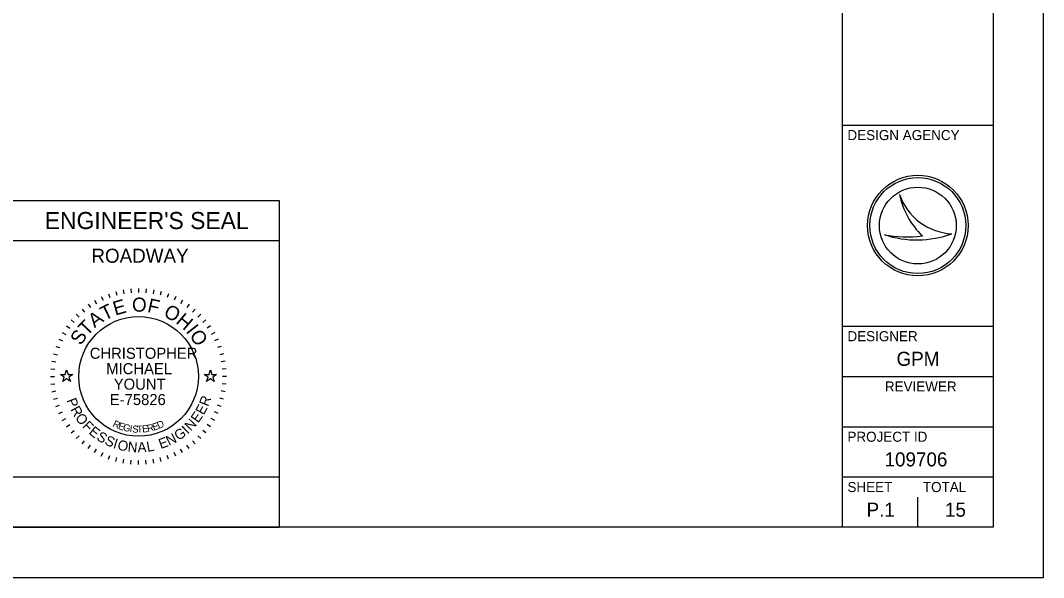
# Model space of a CAD drawing. Extents: x 0 to 34, y 0 to 22.
# Drawn here: x 23.83 to 34, y 0 to 5.54 of the extents above; entities that cross this region are included whole.
import ezdxf

# ---------------------------------------------------------------- set-up
doc = ezdxf.new("R2010")
doc.units = 0
for name, color, linetype in [('Default', 7, 'Continuous'), ('SH_Border', 7, 'Continuous'), ('SH_Cut_Line', 7, 'Continuous'), ('SH_Data', 7, 'Continuous')]:
    doc.layers.add(name, color=color, linetype=linetype)

msp = doc.modelspace()

# ---------------------------------------------------------------- linework, layer by layer
at = {"layer": 'Default'}
for points in [[(24.224, 2.02), (24.271, 2.02), (24.285, 2.065), (24.299, 2.02), (24.346, 2.02), (24.308, 1.992), (24.323, 1.948), (24.285, 1.975), (24.247, 1.948), (24.262, 1.992)], [(25.654, 2.02), (25.701, 2.02), (25.715, 2.065), (25.729, 2.02), (25.776, 2.02), (25.738, 1.992), (25.753, 1.948), (25.715, 1.975), (25.677, 1.948), (25.692, 1.992)]]:
    msp.add_lwpolyline(points, close=True, dxfattribs=at)
at = {"layer": 'SH_Border'}
for p, q in [((32, 0.5), (32, 21.5)), ((32, 4.5), (33.5, 4.5)), ((32, 2.5), (33.5, 2.5)), ((32, 2), (33.5, 2)), ((32, 1.5), (33.5, 1.5)), ((32, 1), (33.5, 1))]:
    msp.add_line(p, q, dxfattribs=at)
msp.add_lwpolyline([(1.5, 21.5), (33.5, 21.5), (33.5, 0.5), (1.5, 0.5)], close=True, dxfattribs=at)
at = {"layer": 'SH_Cut_Line'}
msp.add_lwpolyline([(0, 0), (34, 0), (34, 22), (0, 22)], close=True, dxfattribs=at)
at = {"layer": 'SH_Data'}
for p, q in [((32.567, 3.81), (32.567, 3.81)), ((23.6, 3.75), (26.4, 3.75)), ((26.4, 3.75), (26.4, 0.5)), ((32.75, 3.5), (32.75, 3.5)), ((32.417, 3.41), (32.417, 3.41)), ((33.087, 3.419), (33.087, 3.419)), ((23.6, 3.35), (26.4, 3.35)), ((24.848, 2.862), (24.855, 2.822)), ((24.924, 2.872), (24.927, 2.832)), ((25, 2.875), (25, 2.835)), ((25.076, 2.872), (25.073, 2.832)), ((25.152, 2.862), (25.145, 2.822)), ((24.563, 2.758), (24.583, 2.723)), ((24.63, 2.793), (24.647, 2.757)), ((24.701, 2.822), (24.714, 2.785)), ((24.774, 2.845), (24.784, 2.807)), ((25.226, 2.845), (25.216, 2.807)), ((25.299, 2.822), (25.286, 2.785)), ((25.37, 2.793), (25.353, 2.757)), ((25.437, 2.758), (25.417, 2.723)), ((24.438, 2.67), (24.463, 2.64)), ((24.498, 2.717), (24.521, 2.684)), ((25.502, 2.717), (25.479, 2.684)), ((25.562, 2.67), (25.537, 2.64)), ((24.33, 2.562), (24.36, 2.537)), ((24.381, 2.619), (24.41, 2.59)), ((25.619, 2.619), (25.59, 2.59)), ((25.67, 2.562), (25.64, 2.537)), ((24.283, 2.502), (24.316, 2.479)), ((25.717, 2.502), (25.684, 2.479)), ((24.207, 2.37), (24.243, 2.353)), ((24.242, 2.438), (24.277, 2.418)), ((25.758, 2.438), (25.723, 2.418)), ((25.793, 2.37), (25.757, 2.353)), ((24.178, 2.299), (24.215, 2.286)), ((25.822, 2.299), (25.785, 2.286)), ((24.138, 2.152), (24.178, 2.145)), ((24.155, 2.226), (24.193, 2.216)), ((25.845, 2.226), (25.807, 2.216)), ((25.862, 2.152), (25.822, 2.145)), ((24.128, 2.076), (24.168, 2.073)), ((25.872, 2.076), (25.832, 2.073)), ((24.125, 2), (24.165, 2)), ((25.875, 2), (25.835, 2)), ((24.128, 1.924), (24.168, 1.927)), ((24.138, 1.848), (24.178, 1.855)), ((25.862, 1.848), (25.822, 1.855)), ((25.872, 1.924), (25.832, 1.927)), ((24.155, 1.774), (24.193, 1.784)), ((25.845, 1.774), (25.807, 1.784)), ((24.178, 1.701), (24.215, 1.714)), ((24.207, 1.63), (24.243, 1.647)), ((25.793, 1.63), (25.757, 1.647)), ((25.822, 1.701), (25.785, 1.714)), ((24.242, 1.563), (24.277, 1.583)), ((25.758, 1.563), (25.723, 1.583)), ((24.283, 1.498), (24.316, 1.521)), ((24.33, 1.438), (24.36, 1.463)), ((25.67, 1.438), (25.64, 1.463)), ((25.717, 1.498), (25.684, 1.521)), ((24.381, 1.381), (24.41, 1.41)), ((24.438, 1.33), (24.463, 1.36)), ((25.562, 1.33), (25.537, 1.36)), ((25.619, 1.381), (25.59, 1.41)), ((24.498, 1.283), (24.521, 1.316)), ((24.563, 1.242), (24.583, 1.277)), ((24.63, 1.207), (24.647, 1.243)), ((25.37, 1.207), (25.353, 1.243)), ((25.437, 1.242), (25.417, 1.277)), ((25.502, 1.283), (25.479, 1.316)), ((24.701, 1.178), (24.714, 1.215)), ((24.774, 1.155), (24.784, 1.193)), ((24.848, 1.138), (24.855, 1.178)), ((24.924, 1.128), (24.927, 1.168)), ((25, 1.125), (25, 1.165)), ((25.076, 1.128), (25.073, 1.168)), ((25.152, 1.138), (25.145, 1.178)), ((25.226, 1.155), (25.216, 1.193)), ((25.299, 1.178), (25.286, 1.215)), ((32.75, 0.5), (32.75, 0.8)), ((32.375, 0.675), (32.375, 0.675)), ((23.6, 0.5), (26.4, 0.5))]:
    msp.add_line(p, q, dxfattribs=at)
msp.add_lwpolyline([(23.6, 0.5), (23.6, 1), (26.4, 1), (26.4, 0.5)], close=True, dxfattribs=at)
for centre, radius in [((32.75, 3.5), 0.5), ((32.75, 3.5), 0.477), ((32.75, 3.5), 0.477), ((32.75, 3.5), 0.382), ((25, 2), 0.595)]:
    msp.add_circle(centre, radius, dxfattribs=at)
for centre, radius, start, end in [((33.116, 3.998), 0.58, 198.9257, 198.9319), ((33.347, 3.97), 0.796, 191.6379, 191.6421), ((33.116, 3.998), 0.58, 198.9319, 267.1657), ((33.347, 3.97), 0.796, 191.6421, 226.0947), ((32.739, 4.37), 1.013, 251.4576, 290.0832), ((32.648, 4.654), 1.266, 259.4964, 259.4995), ((32.739, 4.37), 1.013, 251.4527, 251.4576), ((32.648, 4.654), 1.266, 259.4995, 276.6672)]:
    msp.add_arc(centre, radius, start, end, dxfattribs=at)

# ---------------------------------------------------------------- texts
for s, height, p in [('DESIGN AGENCY', 0.1, (32.05, 4.35)), ("ENGINEER'S SEAL", 0.17, (24.068, 3.465)), ('ROADWAY', 0.14, (24.531, 3.13)), ('DESIGNER', 0.1, (32.05, 2.35)), ('CHRISTOPHER', 0.11, (24.515, 2.175)), ('GPM', 0.14, (32.538, 2.105)), ('MICHAEL', 0.11, (24.679, 2.022)), ('YOUNT', 0.11, (24.754, 1.868)), ('REVIEWER', 0.1, (32.422, 1.85)), ('E-75826', 0.11, (24.715, 1.715)), ('PROJECT ID', 0.1, (32.05, 1.35)), ('109706', 0.14, (32.419, 1.105)), ('SHEET', 0.1, (32.05, 0.85)), ('TOTAL', 0.1, (32.8, 0.85)), ('P.1', 0.14, (32.24, 0.605)), ('15', 0.14, (33.02, 0.605))]:
    msp.add_text(s, height=height, dxfattribs=at).set_placement(p)
for s, height, rotation, p in [('E', 0.14, 15.7571, (24.768, 2.604)), ('O', 0.14, 359.7812, (24.935, 2.644)), ('F', 0.14, 347.4362, (25.081, 2.642)), ('T', 0.14, 25.7167, (24.662, 2.552)), ('O', 0.14, 332.2586, (25.24, 2.602)), ('T', 0.14, 46.4344, (24.488, 2.396)), ('A', 0.14, 36.4747, (24.563, 2.478)), ('H', 0.14, 319.9136, (25.363, 2.536)), ('S', 0.14, 57.1924, (24.428, 2.301)), ('I', 0.14, 308.367, (25.466, 2.448)), ('O', 0.14, 303.1491, (25.502, 2.409)), ('P', 0.1, 291.494, (24.282, 1.762)), ('R', 0.1, 69.2322, (25.692, 1.695)), ('R', 0.1, 298.7311, (24.319, 1.672)), ('E', 0.1, 54.758, (25.593, 1.531)), ('E', 0.1, 61.9951, (25.648, 1.61)), ('O', 0.1, 306.4666, (24.365, 1.588)), ('F', 0.1, 314.7068, (24.434, 1.498)), ('R', 0.07, 334.487, (24.737, 1.505)), ('E', 0.07, 341.04, (24.791, 1.48)), ('G', 0.07, 347.4752, (24.841, 1.462)), ('E', 0.07, 17.6836, (25.15, 1.46)), ('D', 0.07, 23.3052, (25.201, 1.477)), ('N', 0.1, 47.0224, (25.52, 1.451)), ('E', 0.1, 321.4393, (24.498, 1.435)), ('S', 0.1, 328.6764, (24.574, 1.375)), ('I', 0.07, 353.7858, (24.909, 1.447)), ('S', 0.07, 356.8926, (24.936, 1.443)), ('T', 0.07, 3.0061, (24.986, 1.439)), ('E', 0.07, 6.0117, (25.039, 1.441)), ('R', 0.07, 11.9184, (25.092, 1.447)), ('N', 0.1, 27.3113, (25.304, 1.308)), ('G', 0.1, 35.0469, (25.398, 1.357)), ('I', 0.1, 43.287, (25.487, 1.421)), ('S', 0.1, 335.9134, (24.656, 1.327)), ('I', 0.1, 343.1505, (24.741, 1.29)), ('O', 0.1, 346.8859, (24.784, 1.275)), ('N', 0.1, 355.1261, (24.889, 1.252)), ('A', 0.1, 2.8617, (24.992, 1.244)), ('L', 0.1, 10.0987, (25.089, 1.249)), ('E', 0.1, 20.0742, (25.221, 1.277))]:
    msp.add_text(s, height=height, rotation=rotation, dxfattribs=at).set_placement(p)

doc.saveas('drawing.dxf')
